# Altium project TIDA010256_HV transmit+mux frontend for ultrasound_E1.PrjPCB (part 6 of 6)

## Sheet 25_RX_Connector.SchDoc
size 431 x 279 mm; Date: Not shown in title block; ApprovedBy: Not shown in title block; CheckedBy: Not shown in title block; Author: Not shown in title block; CompanyName: Not shown in title block; Engineer: Not shown in title block; Organization: Not shown in title block; Address1: Not shown in title block; Address2: Not shown in title block; Address3: Not shown in title block; Address4: Not shown in title block; DocumentNumber: 17; Revision: Use project parameter SCH_Rev; SheetNumber: 17; SheetTotal: 18; PageSetup: Record=PageOptions¦CenterHorizontal=True¦CenterVertical=True¦PrintScale=1.00¦XCorrection=1.00¦YCorrection=1.00¦PrintKind=0¦BorderSize=5000000¦LeftOffset=0¦BottomOffset=0¦Orientation=2¦PaperLength=1000¦PaperWidth=1000¦Scale=100¦PaperSource=15¦PrintQuality=600¦MediaType=1¦DitherType=10¦PaperKind=Letter¦PrintScaleMode=1
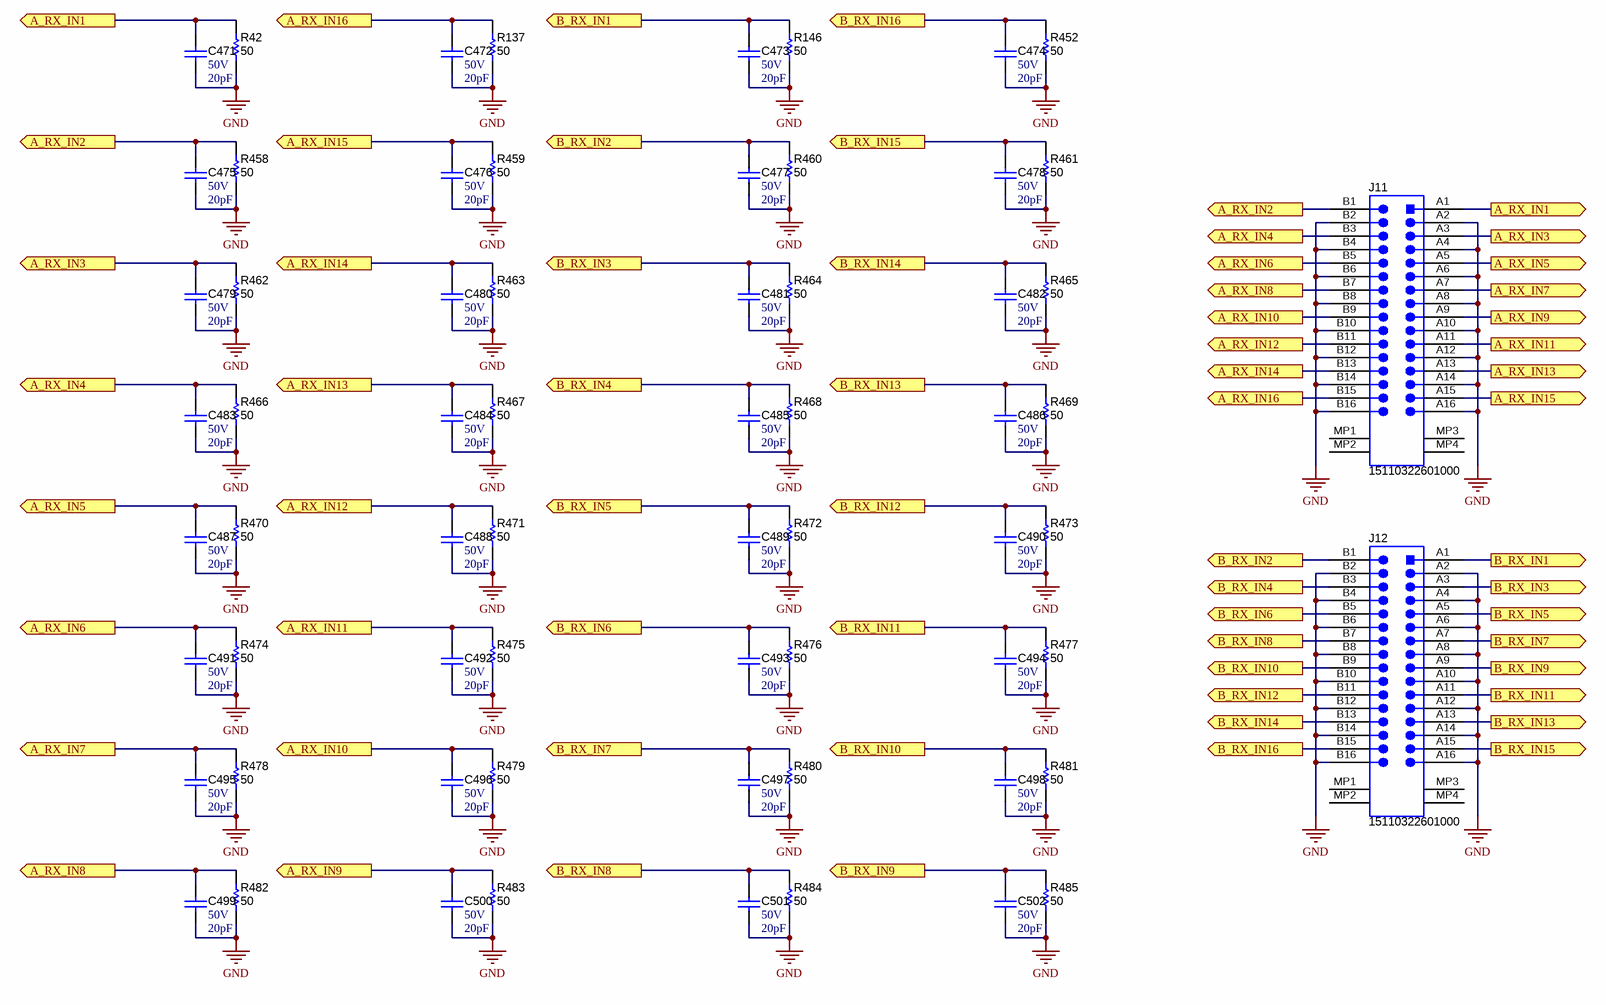
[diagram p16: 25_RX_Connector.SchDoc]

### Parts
C471  VDC_V: 50V  ValueDisplayed: 20pF  [0402]  (hidden comment: C0402C200J5GACTU)
C472  VDC_V: 50V  ValueDisplayed: 20pF  [0402]  (hidden comment: C0402C200J5GACTU)
C473  VDC_V: 50V  ValueDisplayed: 20pF  [0402]  (hidden comment: C0402C200J5GACTU)
C474  VDC_V: 50V  ValueDisplayed: 20pF  [0402]  (hidden comment: C0402C200J5GACTU)
C475  VDC_V: 50V  ValueDisplayed: 20pF  [0402]  (hidden comment: C0402C200J5GACTU)
C476  VDC_V: 50V  ValueDisplayed: 20pF  [0402]  (hidden comment: C0402C200J5GACTU)
C477  VDC_V: 50V  ValueDisplayed: 20pF  [0402]  (hidden comment: C0402C200J5GACTU)
C478  VDC_V: 50V  ValueDisplayed: 20pF  [0402]  (hidden comment: C0402C200J5GACTU)
C479  VDC_V: 50V  ValueDisplayed: 20pF  [0402]  (hidden comment: C0402C200J5GACTU)
C480  VDC_V: 50V  ValueDisplayed: 20pF  [0402]  (hidden comment: C0402C200J5GACTU)
C481  VDC_V: 50V  ValueDisplayed: 20pF  [0402]  (hidden comment: C0402C200J5GACTU)
C482  VDC_V: 50V  ValueDisplayed: 20pF  [0402]  (hidden comment: C0402C200J5GACTU)
C483  VDC_V: 50V  ValueDisplayed: 20pF  [0402]  (hidden comment: C0402C200J5GACTU)
C484  VDC_V: 50V  ValueDisplayed: 20pF  [0402]  (hidden comment: C0402C200J5GACTU)
C485  VDC_V: 50V  ValueDisplayed: 20pF  [0402]  (hidden comment: C0402C200J5GACTU)
C486  VDC_V: 50V  ValueDisplayed: 20pF  [0402]  (hidden comment: C0402C200J5GACTU)
C487  VDC_V: 50V  ValueDisplayed: 20pF  [0402]  (hidden comment: C0402C200J5GACTU)
C488  VDC_V: 50V  ValueDisplayed: 20pF  [0402]  (hidden comment: C0402C200J5GACTU)
C489  VDC_V: 50V  ValueDisplayed: 20pF  [0402]  (hidden comment: C0402C200J5GACTU)
C490  VDC_V: 50V  ValueDisplayed: 20pF  [0402]  (hidden comment: C0402C200J5GACTU)
C491  VDC_V: 50V  ValueDisplayed: 20pF  [0402]  (hidden comment: C0402C200J5GACTU)
C492  VDC_V: 50V  ValueDisplayed: 20pF  [0402]  (hidden comment: C0402C200J5GACTU)
C493  VDC_V: 50V  ValueDisplayed: 20pF  [0402]  (hidden comment: C0402C200J5GACTU)
C494  VDC_V: 50V  ValueDisplayed: 20pF  [0402]  (hidden comment: C0402C200J5GACTU)
C495  VDC_V: 50V  ValueDisplayed: 20pF  [0402]  (hidden comment: C0402C200J5GACTU)
C496  VDC_V: 50V  ValueDisplayed: 20pF  [0402]  (hidden comment: C0402C200J5GACTU)
C497  VDC_V: 50V  ValueDisplayed: 20pF  [0402]  (hidden comment: C0402C200J5GACTU)
C498  VDC_V: 50V  ValueDisplayed: 20pF  [0402]  (hidden comment: C0402C200J5GACTU)
C499  VDC_V: 50V  ValueDisplayed: 20pF  [0402]  (hidden comment: C0402C200J5GACTU)
C500  VDC_V: 50V  ValueDisplayed: 20pF  [0402]  (hidden comment: C0402C200J5GACTU)
C501  VDC_V: 50V  ValueDisplayed: 20pF  [0402]  (hidden comment: C0402C200J5GACTU)
C502  VDC_V: 50V  ValueDisplayed: 20pF  [0402]  (hidden comment: C0402C200J5GACTU)
J11  15110322601000  [Harting_15110322601000]
J12  15110322601000  [Harting_15110322601000]
R42  ValueDisplayed: 50  [0402]  (hidden comment: FC0402E50R0BST1)
R137  ValueDisplayed: 50  [0402]  (hidden comment: FC0402E50R0BST1)
R146  ValueDisplayed: 50  [0402]  (hidden comment: FC0402E50R0BST1)
R452  ValueDisplayed: 50  [0402]  (hidden comment: FC0402E50R0BST1)
R458  ValueDisplayed: 50  [0402]  (hidden comment: FC0402E50R0BST1)
R459  ValueDisplayed: 50  [0402]  (hidden comment: FC0402E50R0BST1)
R460  ValueDisplayed: 50  [0402]  (hidden comment: FC0402E50R0BST1)
R461  ValueDisplayed: 50  [0402]  (hidden comment: FC0402E50R0BST1)
R462  ValueDisplayed: 50  [0402]  (hidden comment: FC0402E50R0BST1)
R463  ValueDisplayed: 50  [0402]  (hidden comment: FC0402E50R0BST1)
R464  ValueDisplayed: 50  [0402]  (hidden comment: FC0402E50R0BST1)
R465  ValueDisplayed: 50  [0402]  (hidden comment: FC0402E50R0BST1)
R466  ValueDisplayed: 50  [0402]  (hidden comment: FC0402E50R0BST1)
R467  ValueDisplayed: 50  [0402]  (hidden comment: FC0402E50R0BST1)
R468  ValueDisplayed: 50  [0402]  (hidden comment: FC0402E50R0BST1)
R469  ValueDisplayed: 50  [0402]  (hidden comment: FC0402E50R0BST1)
R470  ValueDisplayed: 50  [0402]  (hidden comment: FC0402E50R0BST1)
R471  ValueDisplayed: 50  [0402]  (hidden comment: FC0402E50R0BST1)
R472  ValueDisplayed: 50  [0402]  (hidden comment: FC0402E50R0BST1)
R473  ValueDisplayed: 50  [0402]  (hidden comment: FC0402E50R0BST1)
R474  ValueDisplayed: 50  [0402]  (hidden comment: FC0402E50R0BST1)
R475  ValueDisplayed: 50  [0402]  (hidden comment: FC0402E50R0BST1)
R476  ValueDisplayed: 50  [0402]  (hidden comment: FC0402E50R0BST1)
R477  ValueDisplayed: 50  [0402]  (hidden comment: FC0402E50R0BST1)
R478  ValueDisplayed: 50  [0402]  (hidden comment: FC0402E50R0BST1)
R479  ValueDisplayed: 50  [0402]  (hidden comment: FC0402E50R0BST1)
R480  ValueDisplayed: 50  [0402]  (hidden comment: FC0402E50R0BST1)
R481  ValueDisplayed: 50  [0402]  (hidden comment: FC0402E50R0BST1)
R482  ValueDisplayed: 50  [0402]  (hidden comment: FC0402E50R0BST1)
R483  ValueDisplayed: 50  [0402]  (hidden comment: FC0402E50R0BST1)
R484  ValueDisplayed: 50  [0402]  (hidden comment: FC0402E50R0BST1)
R485  ValueDisplayed: 50  [0402]  (hidden comment: FC0402E50R0BST1)

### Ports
A_RX_IN1 (out), A_RX_IN2 (out), A_RX_IN3 (out), A_RX_IN4 (out), A_RX_IN5 (out), A_RX_IN6 (out), A_RX_IN7 (out), A_RX_IN8 (out), A_RX_IN9 (out), A_RX_IN10 (out), A_RX_IN11 (out), A_RX_IN12 (out), A_RX_IN13 (out), A_RX_IN14 (out), A_RX_IN15 (out), A_RX_IN16 (out), B_RX_IN1 (out), B_RX_IN2 (out), B_RX_IN3 (out), B_RX_IN4 (out), B_RX_IN5 (out), B_RX_IN6 (out), B_RX_IN7 (out), B_RX_IN8 (out), B_RX_IN9 (out), B_RX_IN10 (out), B_RX_IN11 (out), B_RX_IN12 (out), B_RX_IN13 (out), B_RX_IN14 (out), B_RX_IN15 (out), B_RX_IN16 (out)

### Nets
GND: C471.2 C472.2 C473.2 C474.2 C475.2 C476.2 C477.2 C478.2 C479.2 C480.2 C481.2 C482.2 C483.2 C484.2 C485.2 C486.2 C487.2 C488.2 C489.2 C490.2 C491.2 C492.2 C493.2 C494.2 C495.2 C496.2 C497.2 C498.2 C499.2 C500.2 C501.2 C502.2 J11.A2 J11.A4 J11.A6 J11.A8 J11.A10 J11.A12 J11.A14 J11.A16 J11.B2 J11.B4 J11.B6 J11.B8 J11.B10 J11.B12 J11.B14 J11.B16 J12.A2 J12.A4 J12.A6 J12.A8 J12.A10 J12.A12 J12.A14 J12.A16 J12.B2 J12.B4 J12.B6 J12.B8 J12.B10 J12.B12 J12.B14 J12.B16 R42.1 R137.1 R146.1 R452.1 R458.1 R459.1 R460.1 R461.1 R462.1 R463.1 R464.1 R465.1 R466.1 R467.1 R468.1 R469.1 R470.1 R471.1 R472.1 R473.1 R474.1 R475.1 R476.1 R477.1 R478.1 R479.1 R480.1 R481.1 R482.1 R483.1 R484.1 R485.1
A_RX_IN1: C471.1 J11.A1 R42.2 ; port A_RX_IN1
A_RX_IN2: C475.1 J11.B1 R458.2 ; port A_RX_IN2
A_RX_IN3: C479.1 J11.A3 R462.2 ; port A_RX_IN3
A_RX_IN4: C483.1 J11.B3 R466.2 ; port A_RX_IN4
A_RX_IN5: C487.1 J11.A5 R470.2 ; port A_RX_IN5
A_RX_IN6: C491.1 J11.B5 R474.2 ; port A_RX_IN6
A_RX_IN7: C495.1 J11.A7 R478.2 ; port A_RX_IN7
A_RX_IN8: C499.1 J11.B7 R482.2 ; port A_RX_IN8
A_RX_IN9: C500.1 J11.A9 R483.2 ; port A_RX_IN9
A_RX_IN10: C496.1 J11.B9 R479.2 ; port A_RX_IN10
A_RX_IN11: C492.1 J11.A11 R475.2 ; port A_RX_IN11
A_RX_IN12: C488.1 J11.B11 R471.2 ; port A_RX_IN12
A_RX_IN13: C484.1 J11.A13 R467.2 ; port A_RX_IN13
A_RX_IN14: C480.1 J11.B13 R463.2 ; port A_RX_IN14
A_RX_IN15: C476.1 J11.A15 R459.2 ; port A_RX_IN15
A_RX_IN16: C472.1 J11.B15 R137.2 ; port A_RX_IN16
B_RX_IN1: C473.1 J12.A1 R146.2 ; port B_RX_IN1
B_RX_IN2: C477.1 J12.B1 R460.2 ; port B_RX_IN2
B_RX_IN3: C481.1 J12.A3 R464.2 ; port B_RX_IN3
B_RX_IN4: C485.1 J12.B3 R468.2 ; port B_RX_IN4
B_RX_IN5: C489.1 J12.A5 R472.2 ; port B_RX_IN5
B_RX_IN6: C493.1 J12.B5 R476.2 ; port B_RX_IN6
B_RX_IN7: C497.1 J12.A7 R480.2 ; port B_RX_IN7
B_RX_IN8: C501.1 J12.B7 R484.2 ; port B_RX_IN8
B_RX_IN9: C502.1 J12.A9 R485.2 ; port B_RX_IN9
B_RX_IN10: C498.1 J12.B9 R481.2 ; port B_RX_IN10
B_RX_IN11: C494.1 J12.A11 R477.2 ; port B_RX_IN11
B_RX_IN12: C490.1 J12.B11 R473.2 ; port B_RX_IN12
B_RX_IN13: C486.1 J12.A13 R469.2 ; port B_RX_IN13
B_RX_IN14: C482.1 J12.B13 R465.2 ; port B_RX_IN14
B_RX_IN15: C478.1 J12.A15 R461.2 ; port B_RX_IN15
B_RX_IN16: C474.1 J12.B15 R452.2 ; port B_RX_IN16

Not connected (* = marked no-connect by the designer): J11 MP1 MP2 MP3 MP4; J12 MP1 MP2 MP3 MP4

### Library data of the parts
C471-C502 = CMP-0006241-2: CAP, CERM, 20 pF, 50 V, +/- 5%, C0G/NP0, 0402; Manufacturer: Kemet; TaMin_C: -55°C; Polarized: N; SizeAreaWB_mm2: 3; Value1: Unknown; U/M: EA; Value: 20pF; TaMax_C: 125°C; SizeZ_mm: 0.6; SizeX_mm: 1; SizeY_mm: 0.5; AEC Category: Q200
J11 J12 = CMP-0084279-1: Header (Shrouded), 1.27mm, 16x2, Gold, SMT; Manufacturer: Harting; Shrouded: Y; Pitch_mm: 1.27; Row_Count: 2; Voltage_V: 500V; Gender: Male
R42 R137 R146 R452 R458-R485 = CMP-0026791-1: RES, 50, 0.1%, 0.05 W, 0402; Manufacturer: Vishay-Dale; Power_W: 50mW; TempCo: 25 ppm/C; Value_Code: 50R0; U/M: EA; Value: 50; SizeX_mm: 1; SizeY_mm: 0.5; SizeZ_mm: 0.6; Value2: 0.05W; CompType: Resistor; AEC Qualified: N; AEC Category: Q200

## Sheet Hardware.SchDoc
size 431 x 279 mm; Date: Not shown in title block; ApprovedBy: Not shown in title block; CheckedBy: Not shown in title block; Author: Not shown in title block; CompanyName: Not shown in title block; DrawnBy: Jason Ding; Engineer: Not shown in title block; Organization: Not shown in title block; Address1: Not shown in title block; Address2: Not shown in title block; Address3: Not shown in title block; Address4: Not shown in title block; DocumentNumber: 18; Revision: Use project parameter SCH_Rev; SheetNumber: 18; SheetTotal: 18; PageSetup: Record=PageOptions¦CenterHorizontal=True¦CenterVertical=True¦PrintScale=1.00¦XCorrection=1.00¦YCorrection=1.00¦PrintKind=0¦BorderSize=5000000¦LeftOffset=0¦BottomOffset=0¦Orientation=2¦PaperLength=1000¦PaperWidth=1000¦Scale=100¦PaperSource=15¦PrintQuality=600¦MediaType=1¦DitherType=10¦PaperKind=Letter¦PrintScaleMode=1
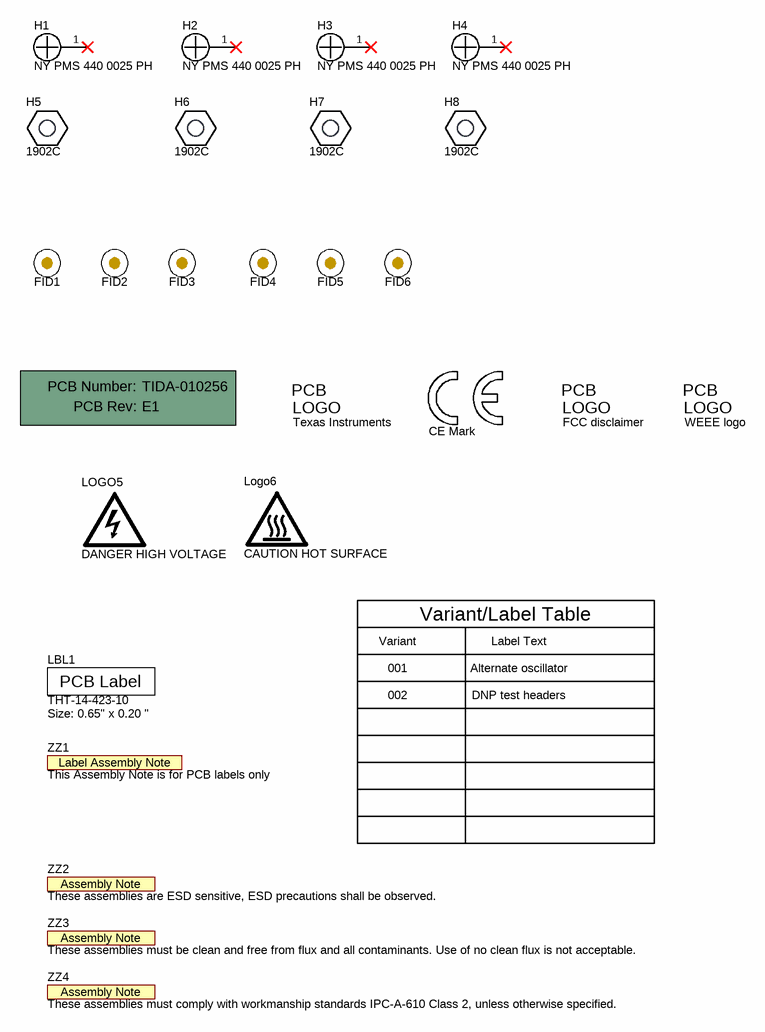
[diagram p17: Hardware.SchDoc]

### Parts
!PCB  Printed Circuit Board  (value not drawn)  (mechanical)
FID1  Fiducial  [Fiducial10-20]  (value not drawn)
FID2  Fiducial  [Fiducial10-20]  (value not drawn)
FID3  Fiducial  [Fiducial10-20]  (value not drawn)
FID4  Fiducial  [Fiducial10-20]  (value not drawn)
FID5  Fiducial  [Fiducial10-20]  (value not drawn)
FID6  Fiducial  [Fiducial10-20]  (value not drawn)
H1  NY PMS 440 0025 PH  [NY PMS 440 0025 PH]
H2  NY PMS 440 0025 PH  [NY PMS 440 0025 PH]
H3  NY PMS 440 0025 PH  [NY PMS 440 0025 PH]
H4  NY PMS 440 0025 PH  [NY PMS 440 0025 PH]
H5  1902C  [Keystone_1902C]
H6  1902C  [Keystone_1902C]
H7  1902C  [Keystone_1902C]
H8  1902C  [Keystone_1902C]
LBL1  THT-14-423-10  Note: Size: 0.65" x 0.20 "  [Label_650x200]
Logo1  Texas Instruments  [TI_Stacked_Overlay_Small]  (no BOM)
Logo2  CE Mark  [CE_Mark_5mm]  (no BOM)
Logo3  FCC disclaimer  [FCC_disclaimer]  (no BOM)
Logo4  WEEE logo  [WEEE_Minimum]  (no BOM)
LOGO5  DANGER HIGH VOLTAGE  [IEC_HighVoltage_Large]  (no BOM)
Logo6  CAUTION HOT SURFACE  [IEC_HotSurface_Large]  (no BOM)
ZZ1  This Assembly Note is for PCB labels only  [AssemblyNoteLabel]  (no BOM)
ZZ2  These assemblies are ESD sensitive, ESD precautions shall be observed.  [AssemblyNote]  (no BOM)
ZZ3  These assemblies must be clean and free from flux and all contaminants. Use of no clean flux is not acceptable.  [AssemblyNote]  (no BOM)
ZZ4  These assemblies must comply with workmanship standards IPC-A-610 Class 2, unless otherwise specified.  [AssemblyNote]  (no BOM)

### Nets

Not connected (* = marked no-connect by the designer): H1 1*; H2 1*; H3 1*; H4 1*

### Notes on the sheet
- Variant
- Variant/Label Table
- Label Text
- 001
- 002
- Alternate oscillator
- DNP test headers

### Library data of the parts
!PCB = CMP-0003618-2: Manufacturer: Any; PartNumber: TIDA-010256
FID1-FID6 = CMP-0077181-1: Fiducial mark.  There is nothing to buy or mount.
H1-H4 = CMP-0003617-1: Machine Screw, Round, #4-40 x 1/4, Nylon, Philips panhead; Manufacturer: B&F Fastener Supply; CompType: Hardware
H5-H8 = CMP-0003610-1: Standoff, Hex, 0.5"L #4-40 Nylon; Manufacturer: Keystone; CompType: Hardware
LBL1 = CMP-0003625-1: Thermal Transfer Printable Labels, 0.650" W x 0.200" H - 10,000 per roll; Manufacturer: Brady; CompType: Label
Logo1 = CMP-0074838-1: Texas Instrument Corporate Signature; SymbolCreator: a0412235; Lib Reference: TI_Logo; Library Reference: Logo
Logo2 = CMP-0074844-1: SymbolCreator: a0412235
Logo3 = CMP-0074847-1: FCC_disclaimer; Library Reference: Logo
Logo4 = CMP-0074769-3: Manufacturer: Texas Instruments; CompType: IC; AEC Category: Q200
LOGO5 = CMP-0074835-1: IEC 61010-1 High Voltage Warning; SymbolCreator: a0412235
Logo6 = CMP-0074837-2: IEC 61010-1 Hot Surface Warning; Manufacturer: Texas Instruments; CompType: IC; AEC Category: Q200; SymbolCreator: a0412235
ZZ1 = CMP-0003616-3
ZZ2 = CMP-0077236-1
ZZ3 = CMP-0077237-1
ZZ4 = CMP-0077238-1

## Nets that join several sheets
GND: 11_HighVoltage_PowerSupply (15 pins), 12_LowVoltage_PowerSupplies01 (82 pins), 13_LowVoltage_PowerSupplies02 (35 pins), 14_XDS110_Debugger (59 pins), 15_AM243x_BootMode (28 pins), 16_AM243x_Reset (28 pins), 17_AM243x_SocPower (137 pins), 18_AM243x_Pinout (37 pins), 19_Clock_Gen (24 pins), 20_TX7516_PartAPinout (82 pins), 21_TX7516_PartBPinout (78 pins), 22_TMUX9832(0-64)_Pinout (38 pins), 23_TMUX9832(65-128)_Pinout (40 pins), 24_TX_Connector(no load resitor) (112 pins), 25_RX_Connector (96 pins)
MHV_A: 11_HighVoltage_PowerSupply (D18.2 D19.2), 20_TX7516_PartAPinout (12 pins), 21_TX7516_PartBPinout (12 pins)
MHV_B: 11_HighVoltage_PowerSupply (D23.2 D24.2), 20_TX7516_PartAPinout (12 pins), 21_TX7516_PartBPinout (12 pins)
PHV_A: 11_HighVoltage_PowerSupply (D15.1 D17.1), 20_TX7516_PartAPinout (12 pins), 21_TX7516_PartBPinout (12 pins)
PHV_B: 11_HighVoltage_PowerSupply (D20.1 D22.1), 20_TX7516_PartAPinout (12 pins), 21_TX7516_PartBPinout (12 pins)
V_+12V: 11_HighVoltage_PowerSupply (12 pins), 12_LowVoltage_PowerSupplies01 (21 pins), 13_LowVoltage_PowerSupplies02 (7 pins)
A_RX_IN1: 20_TX7516_PartAPinout (U25.L12), 25_RX_Connector (C471.1 J11.A1 R42.2)
A_RX_IN2: 20_TX7516_PartAPinout (U25.M12), 25_RX_Connector (C475.1 J11.B1 R458.2)
A_RX_IN3: 20_TX7516_PartAPinout (U25.L11), 25_RX_Connector (C479.1 J11.A3 R462.2)
A_RX_IN4: 20_TX7516_PartAPinout (U25.M11), 25_RX_Connector (C483.1 J11.B3 R466.2)
A_RX_IN5: 20_TX7516_PartAPinout (U25.L10), 25_RX_Connector (C487.1 J11.A5 R470.2)
A_RX_IN6: 20_TX7516_PartAPinout (U25.M10), 25_RX_Connector (C491.1 J11.B5 R474.2)
A_RX_IN7: 20_TX7516_PartAPinout (U25.L9), 25_RX_Connector (C495.1 J11.A7 R478.2)
A_RX_IN8: 20_TX7516_PartAPinout (U25.M9), 25_RX_Connector (C499.1 J11.B7 R482.2)
A_RX_IN9: 20_TX7516_PartAPinout (U25.L4), 25_RX_Connector (C500.1 J11.A9 R483.2)
A_RX_IN10: 20_TX7516_PartAPinout (U25.M4), 25_RX_Connector (C496.1 J11.B9 R479.2)
A_RX_IN11: 20_TX7516_PartAPinout (U25.L3), 25_RX_Connector (C492.1 J11.A11 R475.2)
A_RX_IN12: 20_TX7516_PartAPinout (U25.M3), 25_RX_Connector (C488.1 J11.B11 R471.2)
A_RX_IN13: 20_TX7516_PartAPinout (U25.L2), 25_RX_Connector (C484.1 J11.A13 R467.2)
A_RX_IN14: 20_TX7516_PartAPinout (U25.M2), 25_RX_Connector (C480.1 J11.B13 R463.2)
A_RX_IN15: 20_TX7516_PartAPinout (U25.L1), 25_RX_Connector (C476.1 J11.A15 R459.2)
A_RX_IN16: 20_TX7516_PartAPinout (U25.M1), 25_RX_Connector (C472.1 J11.B15 R137.2)
A_TX_OUT1: 20_TX7516_PartAPinout (U25.A12), 22_TMUX9832(0-64)_Pinout (J14.1 U28.K2 U29.K2), 23_TMUX9832(65-128)_Pinout (J16.1 U27.K2 U30.K2)
A_TX_OUT2: 20_TX7516_PartAPinout (U25.B12), 22_TMUX9832(0-64)_Pinout (U28.L3 U29.L3), 23_TMUX9832(65-128)_Pinout (U27.L3 U30.L3)
A_TX_OUT3: 20_TX7516_PartAPinout (U25.C12), 22_TMUX9832(0-64)_Pinout (J13.1 U28.K3 U29.K3), 23_TMUX9832(65-128)_Pinout (U27.K3 U30.K3)
A_TX_OUT4: 20_TX7516_PartAPinout (U25.A11), 22_TMUX9832(0-64)_Pinout (U28.L4 U29.L4), 23_TMUX9832(65-128)_Pinout (U27.L4 U30.L4)
A_TX_OUT5: 20_TX7516_PartAPinout (U25.B11), 22_TMUX9832(0-64)_Pinout (U28.K4 U29.K4), 23_TMUX9832(65-128)_Pinout (U27.K4 U30.K4)
A_TX_OUT6: 20_TX7516_PartAPinout (U25.C11), 22_TMUX9832(0-64)_Pinout (U28.L5 U29.L5), 23_TMUX9832(65-128)_Pinout (U27.L5 U30.L5)
A_TX_OUT7: 20_TX7516_PartAPinout (U25.A10), 22_TMUX9832(0-64)_Pinout (U28.K5 U29.K5), 23_TMUX9832(65-128)_Pinout (U27.K5 U30.K5)
A_TX_OUT8: 20_TX7516_PartAPinout (U25.B10), 22_TMUX9832(0-64)_Pinout (U28.L6 U29.L6), 23_TMUX9832(65-128)_Pinout (U27.L6 U30.L6)
A_TX_OUT9: 20_TX7516_PartAPinout (U25.A1), 22_TMUX9832(0-64)_Pinout (U28.B5 U29.B5), 23_TMUX9832(65-128)_Pinout (U27.B5 U30.B5)
A_TX_OUT10: 20_TX7516_PartAPinout (U25.B1), 22_TMUX9832(0-64)_Pinout (U28.A5 U29.A5), 23_TMUX9832(65-128)_Pinout (U27.A5 U30.A5)
A_TX_OUT11: 20_TX7516_PartAPinout (U25.C1), 22_TMUX9832(0-64)_Pinout (U28.B4 U29.B4), 23_TMUX9832(65-128)_Pinout (U27.B4 U30.B4)
A_TX_OUT12: 20_TX7516_PartAPinout (U25.A2), 22_TMUX9832(0-64)_Pinout (U28.A4 U29.A4), 23_TMUX9832(65-128)_Pinout (U27.A4 U30.A4)
A_TX_OUT13: 20_TX7516_PartAPinout (U25.B2), 22_TMUX9832(0-64)_Pinout (U28.B3 U29.B3), 23_TMUX9832(65-128)_Pinout (U27.B3 U30.B3)
A_TX_OUT14: 20_TX7516_PartAPinout (U25.C2), 22_TMUX9832(0-64)_Pinout (U28.A3 U29.A3), 23_TMUX9832(65-128)_Pinout (U27.A3 U30.A3)
A_TX_OUT15: 20_TX7516_PartAPinout (U25.A3), 22_TMUX9832(0-64)_Pinout (U28.A1 U29.A1), 23_TMUX9832(65-128)_Pinout (U27.A1 U30.A1)
A_TX_OUT16: 20_TX7516_PartAPinout (U25.B3), 22_TMUX9832(0-64)_Pinout (U28.B1 U29.B1), 23_TMUX9832(65-128)_Pinout (U27.B1 U30.B1)
B_RX_IN1: 21_TX7516_PartBPinout (U26.L12), 25_RX_Connector (C473.1 J12.A1 R146.2)
B_RX_IN2: 21_TX7516_PartBPinout (U26.M12), 25_RX_Connector (C477.1 J12.B1 R460.2)
B_RX_IN3: 21_TX7516_PartBPinout (U26.L11), 25_RX_Connector (C481.1 J12.A3 R464.2)
B_RX_IN4: 21_TX7516_PartBPinout (U26.M11), 25_RX_Connector (C485.1 J12.B3 R468.2)
B_RX_IN5: 21_TX7516_PartBPinout (U26.L10), 25_RX_Connector (C489.1 J12.A5 R472.2)
B_RX_IN6: 21_TX7516_PartBPinout (U26.M10), 25_RX_Connector (C493.1 J12.B5 R476.2)
B_RX_IN7: 21_TX7516_PartBPinout (U26.L9), 25_RX_Connector (C497.1 J12.A7 R480.2)
B_RX_IN8: 21_TX7516_PartBPinout (U26.M9), 25_RX_Connector (C501.1 J12.B7 R484.2)
B_RX_IN9: 21_TX7516_PartBPinout (U26.L4), 25_RX_Connector (C502.1 J12.A9 R485.2)
B_RX_IN10: 21_TX7516_PartBPinout (U26.M4), 25_RX_Connector (C498.1 J12.B9 R481.2)
B_RX_IN11: 21_TX7516_PartBPinout (U26.L3), 25_RX_Connector (C494.1 J12.A11 R477.2)
B_RX_IN12: 21_TX7516_PartBPinout (U26.M3), 25_RX_Connector (C490.1 J12.B11 R473.2)
B_RX_IN13: 21_TX7516_PartBPinout (U26.L2), 25_RX_Connector (C486.1 J12.A13 R469.2)
B_RX_IN14: 21_TX7516_PartBPinout (U26.M2), 25_RX_Connector (C482.1 J12.B13 R465.2)
B_RX_IN15: 21_TX7516_PartBPinout (U26.L1), 25_RX_Connector (C478.1 J12.A15 R461.2)
B_RX_IN16: 21_TX7516_PartBPinout (U26.M1), 25_RX_Connector (C474.1 J12.B15 R452.2)
B_SYNC_N: 20_TX7516_PartAPinout (R431.1 R432.1 R433.2), 21_TX7516_PartBPinout (U26.L6)
B_SYNC_P: 20_TX7516_PartAPinout (R430.2 R431.2 R432.2), 21_TX7516_PartBPinout (U26.L7)
B_TX_OUT1: 21_TX7516_PartBPinout (U26.A12), 22_TMUX9832(0-64)_Pinout (U28.B11 U29.B11), 23_TMUX9832(65-128)_Pinout (U27.B11 U30.B11)
B_TX_OUT2: 21_TX7516_PartBPinout (U26.B12), 22_TMUX9832(0-64)_Pinout (U28.A11 U29.A11), 23_TMUX9832(65-128)_Pinout (U27.A11 U30.A11)
B_TX_OUT3: 21_TX7516_PartBPinout (U26.C12), 22_TMUX9832(0-64)_Pinout (U28.A9 U29.A9), 23_TMUX9832(65-128)_Pinout (U27.A9 U30.A9)
B_TX_OUT4: 21_TX7516_PartBPinout (U26.A11), 22_TMUX9832(0-64)_Pinout (U28.B9 U29.B9), 23_TMUX9832(65-128)_Pinout (U27.B9 U30.B9)
B_TX_OUT5: 21_TX7516_PartBPinout (U26.B11), 22_TMUX9832(0-64)_Pinout (U28.A8 U29.A8), 23_TMUX9832(65-128)_Pinout (U27.A8 U30.A8)
B_TX_OUT6: 21_TX7516_PartBPinout (U26.C11), 22_TMUX9832(0-64)_Pinout (U28.B8 U29.B8), 23_TMUX9832(65-128)_Pinout (U27.B8 U30.B8)
B_TX_OUT7: 21_TX7516_PartBPinout (U26.A10), 22_TMUX9832(0-64)_Pinout (U28.A7 U29.A7), 23_TMUX9832(65-128)_Pinout (U27.A7 U30.A7)
B_TX_OUT8: 21_TX7516_PartBPinout (U26.B10), 22_TMUX9832(0-64)_Pinout (U28.B7 U29.B7), 23_TMUX9832(65-128)_Pinout (U27.B7 U30.B7)
B_TX_OUT9: 21_TX7516_PartBPinout (U26.A1), 22_TMUX9832(0-64)_Pinout (U28.K6 U29.K6), 23_TMUX9832(65-128)_Pinout (U27.K6 U30.K6)
B_TX_OUT10: 21_TX7516_PartBPinout (U26.B1), 22_TMUX9832(0-64)_Pinout (U28.K7 U29.K7), 23_TMUX9832(65-128)_Pinout (U27.K7 U30.K7)
B_TX_OUT11: 21_TX7516_PartBPinout (U26.C1), 22_TMUX9832(0-64)_Pinout (U28.L7 U29.L7), 23_TMUX9832(65-128)_Pinout (U27.L7 U30.L7)
B_TX_OUT12: 21_TX7516_PartBPinout (U26.A2), 22_TMUX9832(0-64)_Pinout (U28.K8 U29.K8), 23_TMUX9832(65-128)_Pinout (U27.K8 U30.K8)
B_TX_OUT13: 21_TX7516_PartBPinout (U26.B2), 22_TMUX9832(0-64)_Pinout (U28.L8 U29.L8), 23_TMUX9832(65-128)_Pinout (U27.L8 U30.L8)
B_TX_OUT14: 21_TX7516_PartBPinout (U26.C2), 22_TMUX9832(0-64)_Pinout (U28.K9 U29.K9), 23_TMUX9832(65-128)_Pinout (U27.K9 U30.K9)
B_TX_OUT15: 21_TX7516_PartBPinout (U26.A3), 22_TMUX9832(0-64)_Pinout (U28.L9 U29.L9), 23_TMUX9832(65-128)_Pinout (U27.L9 U30.L9)
B_TX_OUT16: 21_TX7516_PartBPinout (U26.B3), 22_TMUX9832(0-64)_Pinout (U28.K10 U29.K10), 23_TMUX9832(65-128)_Pinout (J18.1 U27.K10 U30.K10)
LP_3: 22_TMUX9832(0-64)_Pinout (R509.2 U28.G6), 23_TMUX9832(65-128)_Pinout (R502.1)
NetC96_1: 13_LowVoltage_PowerSupplies02 (C96.1 U11.5), 17_AM243x_SocPower (U17.E16)
NetQ2_1: 11_HighVoltage_PowerSupply (Q2.1 Q4.1 R20.2 R32.2), 18_AM243x_Pinout (U17.Y15)
NetQ5_3: 15_AM243x_BootMode (Q5.3 R123.2), 18_AM243x_Pinout (U17.AA14)
NetQ6_3: 15_AM243x_BootMode (Q6.3 R124.2), 18_AM243x_Pinout (U17.AA13)
NetR1_1: 11_HighVoltage_PowerSupply (R1.1 R6.1 U1.2 U2.2), 18_AM243x_Pinout (U35.8)
NetR2_1: 11_HighVoltage_PowerSupply (R2.1 R7.1 U1.3 U2.3), 18_AM243x_Pinout (U35.1)
NetR54_1: 12_LowVoltage_PowerSupplies01 (R54.1 U32.4), 13_LowVoltage_PowerSupplies02 (R67.2)
NetR58_2: 12_LowVoltage_PowerSupplies01 (R58.2), 13_LowVoltage_PowerSupplies02 (R63.1 U9.4)
NetR81_1: 14_XDS110_Debugger (R81.1 U15.6), 18_AM243x_Pinout (U17.B11)
NetR428_2: 18_AM243x_Pinout (R428.2 U17.E2), 20_TX7516_PartAPinout (R515.1 U31.7)
NetR429_2: 18_AM243x_Pinout (R429.2 U17.D1), 20_TX7516_PartAPinout (R516.1 U31.15)
NetR438_2: 18_AM243x_Pinout (U17.F2), 20_TX7516_PartAPinout (R438.2 U31.4)
NetR439_2: 18_AM243x_Pinout (U17.E1), 20_TX7516_PartAPinout (R439.2 U31.12)
NetR443_1: 15_AM243x_BootMode (R443.1), 18_AM243x_Pinout (U17.P20)
NetR445_1: 15_AM243x_BootMode (R445.1 U33.7), 18_AM243x_Pinout (U17.L20)
NetR446_1: 15_AM243x_BootMode (R446.1 U34.1), 18_AM243x_Pinout (U17.M20)
NetR447_1: 15_AM243x_BootMode (R447.1), 16_AM243x_Reset (R448.2 U17.A6)
NetR488_1: 18_AM243x_Pinout (U17.G2), 22_TMUX9832(0-64)_Pinout (R488.1)
NetR492_2: 22_TMUX9832(0-64)_Pinout (R492.2), 23_TMUX9832(65-128)_Pinout (U27.H4)
NetR504_1: 22_TMUX9832(0-64)_Pinout (U28.F7), 23_TMUX9832(65-128)_Pinout (R504.1)
NetR513_2: 18_AM243x_Pinout (R513.2 U17.B7), 20_TX7516_PartAPinout (U25.H4)
NetR514_2: 18_AM243x_Pinout (R514.2 U17.B9), 21_TX7516_PartBPinout (U26.H4)
NetU12_35: 14_XDS110_Debugger (U12.35), 18_AM243x_Pinout (U20.13)
NetU12_36: 14_XDS110_Debugger (U12.36), 18_AM243x_Pinout (U20.11)
NetU12_37: 14_XDS110_Debugger (U12.37), 18_AM243x_Pinout (U21.7)
NetU12_38: 14_XDS110_Debugger (U12.38), 18_AM243x_Pinout (U20.12)
NetU12_40: 14_XDS110_Debugger (U12.40), 18_AM243x_Pinout (U20.10)
NetU12_42: 14_XDS110_Debugger (U12.42), 18_AM243x_Pinout (U22.8)
NetU12_43: 14_XDS110_Debugger (U12.43), 18_AM243x_Pinout (U22.1)
NetU15_4: 14_XDS110_Debugger (U15.4), 18_AM243x_Pinout (U17.B10)
NetU17_A8: 18_AM243x_Pinout (U17.A8), 20_TX7516_PartAPinout (U25.H9), 21_TX7516_PartBPinout (U26.H9)
NetU17_A17: 18_AM243x_Pinout (U17.A17), 20_TX7516_PartAPinout (U25.J12), 21_TX7516_PartBPinout (U26.J12)
NetU17_B8: 18_AM243x_Pinout (U17.B8), 20_TX7516_PartAPinout (U25.H6), 21_TX7516_PartBPinout (U26.H6)
NetU17_B15: 18_AM243x_Pinout (U17.B15), 20_TX7516_PartAPinout (U25.G4), 21_TX7516_PartBPinout (U26.G4)
NetU17_B16: 18_AM243x_Pinout (U17.B16), 20_TX7516_PartAPinout (U25.J1), 21_TX7516_PartBPinout (U26.J1)
NetU17_C9: 18_AM243x_Pinout (U17.C9), 20_TX7516_PartAPinout (U25.H12), 21_TX7516_PartBPinout (U26.H12)
NetU17_L19: 15_AM243x_BootMode (U33.15), 18_AM243x_Pinout (U17.L19)
NetU17_L21: 15_AM243x_BootMode (U33.9), 18_AM243x_Pinout (U17.L21)
NetU17_N1: 18_AM243x_Pinout (U17.N1), 22_TMUX9832(0-64)_Pinout (U29.H4)
NetU17_N3: 18_AM243x_Pinout (U17.N3), 22_TMUX9832(0-64)_Pinout (U29.F5)
NetU17_N19: 15_AM243x_BootMode (U33.1), 18_AM243x_Pinout (U17.N19)
NetU17_N20: 15_AM243x_BootMode (U33.8), 18_AM243x_Pinout (U17.N20)
TX1_CLK_N: 19_Clock_Gen (U23.7), 20_TX7516_PartAPinout (C238.2)
TX1_CLK_P: 19_Clock_Gen (U23.6), 20_TX7516_PartAPinout (C237.2)
TX2_CLK_N: 19_Clock_Gen (U23.4), 21_TX7516_PartBPinout (C269.2)
TX2_CLK_P: 19_Clock_Gen (U23.3), 21_TX7516_PartBPinout (C268.2)
TX_OUT1: 22_TMUX9832(0-64)_Pinout (J7.1 U29.L1), 24_TX_Connector(no load resitor) (J10.2)
TX_OUT2: 22_TMUX9832(0-64)_Pinout (U29.K1), 24_TX_Connector(no load resitor) (J9.119)
TX_OUT3: 22_TMUX9832(0-64)_Pinout (J8.1 U29.J2), 24_TX_Connector(no load resitor) (J10.4)
TX_OUT4: 22_TMUX9832(0-64)_Pinout (U29.J1), 24_TX_Connector(no load resitor) (J9.117)
TX_OUT5: 22_TMUX9832(0-64)_Pinout (U29.H2), 24_TX_Connector(no load resitor) (J10.8)
TX_OUT6: 22_TMUX9832(0-64)_Pinout (U29.H1), 24_TX_Connector(no load resitor) (J9.113)
TX_OUT7: 22_TMUX9832(0-64)_Pinout (U29.G2), 24_TX_Connector(no load resitor) (J10.12)
TX_OUT8: 22_TMUX9832(0-64)_Pinout (U29.G1), 24_TX_Connector(no load resitor) (J9.109)
TX_OUT9: 22_TMUX9832(0-64)_Pinout (U29.F2), 24_TX_Connector(no load resitor) (J10.16)
TX_OUT10: 22_TMUX9832(0-64)_Pinout (U29.F1), 24_TX_Connector(no load resitor) (J9.105)
TX_OUT11: 22_TMUX9832(0-64)_Pinout (U29.E2), 24_TX_Connector(no load resitor) (J10.20)
TX_OUT12: 22_TMUX9832(0-64)_Pinout (U29.E1), 24_TX_Connector(no load resitor) (J9.101)
TX_OUT13: 22_TMUX9832(0-64)_Pinout (U29.D2), 24_TX_Connector(no load resitor) (J10.24)
TX_OUT14: 22_TMUX9832(0-64)_Pinout (U29.D1), 24_TX_Connector(no load resitor) (J9.97)
TX_OUT15: 22_TMUX9832(0-64)_Pinout (U29.C2), 24_TX_Connector(no load resitor) (J10.28)
TX_OUT16: 22_TMUX9832(0-64)_Pinout (U29.C1), 24_TX_Connector(no load resitor) (J9.93)
TX_OUT17: 22_TMUX9832(0-64)_Pinout (U29.C11), 24_TX_Connector(no load resitor) (J10.32)
TX_OUT18: 22_TMUX9832(0-64)_Pinout (U29.C10), 24_TX_Connector(no load resitor) (J9.89)
TX_OUT19: 22_TMUX9832(0-64)_Pinout (U29.D11), 24_TX_Connector(no load resitor) (J10.36)
TX_OUT20: 22_TMUX9832(0-64)_Pinout (U29.D10), 24_TX_Connector(no load resitor) (J9.85)
TX_OUT21: 22_TMUX9832(0-64)_Pinout (U29.E11), 24_TX_Connector(no load resitor) (J10.40)
TX_OUT22: 22_TMUX9832(0-64)_Pinout (U29.E10), 24_TX_Connector(no load resitor) (J9.81)
TX_OUT23: 22_TMUX9832(0-64)_Pinout (U29.F11), 24_TX_Connector(no load resitor) (J10.44)
TX_OUT24: 22_TMUX9832(0-64)_Pinout (U29.F10), 24_TX_Connector(no load resitor) (J9.77)
TX_OUT25: 22_TMUX9832(0-64)_Pinout (U29.G11), 24_TX_Connector(no load resitor) (J10.48)
TX_OUT26: 22_TMUX9832(0-64)_Pinout (U29.G10), 24_TX_Connector(no load resitor) (J9.73)
TX_OUT27: 22_TMUX9832(0-64)_Pinout (U29.H11), 24_TX_Connector(no load resitor) (J10.52)
TX_OUT28: 22_TMUX9832(0-64)_Pinout (U29.H10), 24_TX_Connector(no load resitor) (J9.69)
TX_OUT29: 22_TMUX9832(0-64)_Pinout (U29.J11), 24_TX_Connector(no load resitor) (J10.56)
TX_OUT30: 22_TMUX9832(0-64)_Pinout (U29.J10), 24_TX_Connector(no load resitor) (J9.65)
TX_OUT31: 22_TMUX9832(0-64)_Pinout (U29.K11), 24_TX_Connector(no load resitor) (J10.60)
TX_OUT32: 22_TMUX9832(0-64)_Pinout (U29.L11), 24_TX_Connector(no load resitor) (J9.61)
TX_OUT33: 22_TMUX9832(0-64)_Pinout (U28.L1), 24_TX_Connector(no load resitor) (J10.1)
TX_OUT34: 22_TMUX9832(0-64)_Pinout (U28.K1), 24_TX_Connector(no load resitor) (J9.120)
TX_OUT35: 22_TMUX9832(0-64)_Pinout (U28.J2), 24_TX_Connector(no load resitor) (J10.3)
TX_OUT36: 22_TMUX9832(0-64)_Pinout (U28.J1), 24_TX_Connector(no load resitor) (J9.118)
TX_OUT37: 22_TMUX9832(0-64)_Pinout (U28.H2), 24_TX_Connector(no load resitor) (J10.7)
TX_OUT38: 22_TMUX9832(0-64)_Pinout (U28.H1), 24_TX_Connector(no load resitor) (J9.114)
TX_OUT39: 22_TMUX9832(0-64)_Pinout (U28.G2), 24_TX_Connector(no load resitor) (J10.11)
TX_OUT40: 22_TMUX9832(0-64)_Pinout (U28.G1), 24_TX_Connector(no load resitor) (J9.110)
TX_OUT41: 22_TMUX9832(0-64)_Pinout (U28.F2), 24_TX_Connector(no load resitor) (J10.15)
TX_OUT42: 22_TMUX9832(0-64)_Pinout (U28.F1), 24_TX_Connector(no load resitor) (J9.106)
TX_OUT43: 22_TMUX9832(0-64)_Pinout (U28.E2), 24_TX_Connector(no load resitor) (J10.19)
TX_OUT44: 22_TMUX9832(0-64)_Pinout (U28.E1), 24_TX_Connector(no load resitor) (J9.102)
TX_OUT45: 22_TMUX9832(0-64)_Pinout (U28.D2), 24_TX_Connector(no load resitor) (J10.23)
TX_OUT46: 22_TMUX9832(0-64)_Pinout (U28.D1), 24_TX_Connector(no load resitor) (J9.98)
TX_OUT47: 22_TMUX9832(0-64)_Pinout (U28.C2), 24_TX_Connector(no load resitor) (J10.27)
TX_OUT48: 22_TMUX9832(0-64)_Pinout (U28.C1), 24_TX_Connector(no load resitor) (J9.94)
TX_OUT49: 22_TMUX9832(0-64)_Pinout (U28.C11), 24_TX_Connector(no load resitor) (J10.31)
TX_OUT50: 22_TMUX9832(0-64)_Pinout (U28.C10), 24_TX_Connector(no load resitor) (J9.90)
TX_OUT51: 22_TMUX9832(0-64)_Pinout (U28.D11), 24_TX_Connector(no load resitor) (J10.35)
TX_OUT52: 22_TMUX9832(0-64)_Pinout (U28.D10), 24_TX_Connector(no load resitor) (J9.86)
TX_OUT53: 22_TMUX9832(0-64)_Pinout (U28.E11), 24_TX_Connector(no load resitor) (J10.39)
TX_OUT54: 22_TMUX9832(0-64)_Pinout (U28.E10), 24_TX_Connector(no load resitor) (J9.82)
TX_OUT55: 22_TMUX9832(0-64)_Pinout (U28.F11), 24_TX_Connector(no load resitor) (J10.43)
TX_OUT56: 22_TMUX9832(0-64)_Pinout (U28.F10), 24_TX_Connector(no load resitor) (J9.78)
TX_OUT57: 22_TMUX9832(0-64)_Pinout (U28.G11), 24_TX_Connector(no load resitor) (J10.47)
TX_OUT58: 22_TMUX9832(0-64)_Pinout (U28.G10), 24_TX_Connector(no load resitor) (J9.74)
TX_OUT59: 22_TMUX9832(0-64)_Pinout (U28.H11), 24_TX_Connector(no load resitor) (J10.51)
TX_OUT60: 22_TMUX9832(0-64)_Pinout (U28.H10), 24_TX_Connector(no load resitor) (J9.70)
TX_OUT61: 22_TMUX9832(0-64)_Pinout (U28.J11), 24_TX_Connector(no load resitor) (J10.55)
TX_OUT62: 22_TMUX9832(0-64)_Pinout (U28.J10), 24_TX_Connector(no load resitor) (J9.66)
TX_OUT63: 22_TMUX9832(0-64)_Pinout (U28.K11), 24_TX_Connector(no load resitor) (J10.59)
TX_OUT64: 22_TMUX9832(0-64)_Pinout (U28.L11), 24_TX_Connector(no load resitor) (J9.62)
TX_OUT65: 23_TMUX9832(65-128)_Pinout (U27.L1), 24_TX_Connector(no load resitor) (J10.62)
TX_OUT66: 23_TMUX9832(65-128)_Pinout (U27.K1), 24_TX_Connector(no load resitor) (J9.59)
TX_OUT67: 23_TMUX9832(65-128)_Pinout (U27.J2), 24_TX_Connector(no load resitor) (J10.66)
TX_OUT68: 23_TMUX9832(65-128)_Pinout (U27.J1), 24_TX_Connector(no load resitor) (J9.55)
TX_OUT69: 23_TMUX9832(65-128)_Pinout (U27.H2), 24_TX_Connector(no load resitor) (J10.70)
TX_OUT70: 23_TMUX9832(65-128)_Pinout (U27.H1), 24_TX_Connector(no load resitor) (J9.51)
TX_OUT71: 23_TMUX9832(65-128)_Pinout (U27.G2), 24_TX_Connector(no load resitor) (J10.74)
TX_OUT72: 23_TMUX9832(65-128)_Pinout (U27.G1), 24_TX_Connector(no load resitor) (J9.47)
TX_OUT73: 23_TMUX9832(65-128)_Pinout (U27.F2), 24_TX_Connector(no load resitor) (J10.78)
TX_OUT74: 23_TMUX9832(65-128)_Pinout (U27.F1), 24_TX_Connector(no load resitor) (J9.43)
TX_OUT75: 23_TMUX9832(65-128)_Pinout (U27.E2), 24_TX_Connector(no load resitor) (J10.82)
TX_OUT76: 23_TMUX9832(65-128)_Pinout (U27.E1), 24_TX_Connector(no load resitor) (J9.39)
TX_OUT77: 23_TMUX9832(65-128)_Pinout (U27.D2), 24_TX_Connector(no load resitor) (J10.86)
TX_OUT78: 23_TMUX9832(65-128)_Pinout (U27.D1), 24_TX_Connector(no load resitor) (J9.35)
TX_OUT79: 23_TMUX9832(65-128)_Pinout (U27.C2), 24_TX_Connector(no load resitor) (J10.90)
TX_OUT80: 23_TMUX9832(65-128)_Pinout (U27.C1), 24_TX_Connector(no load resitor) (J9.31)
TX_OUT81: 23_TMUX9832(65-128)_Pinout (U27.C11), 24_TX_Connector(no load resitor) (J10.94)
TX_OUT82: 23_TMUX9832(65-128)_Pinout (U27.C10), 24_TX_Connector(no load resitor) (J9.27)
TX_OUT83: 23_TMUX9832(65-128)_Pinout (U27.D11), 24_TX_Connector(no load resitor) (J10.98)
TX_OUT84: 23_TMUX9832(65-128)_Pinout (U27.D10), 24_TX_Connector(no load resitor) (J9.23)
TX_OUT85: 23_TMUX9832(65-128)_Pinout (U27.E11), 24_TX_Connector(no load resitor) (J10.102)
TX_OUT86: 23_TMUX9832(65-128)_Pinout (U27.E10), 24_TX_Connector(no load resitor) (J9.19)
TX_OUT87: 23_TMUX9832(65-128)_Pinout (U27.F11), 24_TX_Connector(no load resitor) (J10.106)
TX_OUT88: 23_TMUX9832(65-128)_Pinout (U27.F10), 24_TX_Connector(no load resitor) (J9.15)
TX_OUT89: 23_TMUX9832(65-128)_Pinout (U27.G11), 24_TX_Connector(no load resitor) (J10.110)
TX_OUT90: 23_TMUX9832(65-128)_Pinout (U27.G10), 24_TX_Connector(no load resitor) (J9.11)
TX_OUT91: 23_TMUX9832(65-128)_Pinout (U27.H11), 24_TX_Connector(no load resitor) (J10.114)
TX_OUT92: 23_TMUX9832(65-128)_Pinout (U27.H10), 24_TX_Connector(no load resitor) (J9.7)
TX_OUT93: 23_TMUX9832(65-128)_Pinout (U27.J11), 24_TX_Connector(no load resitor) (J10.118)
TX_OUT94: 23_TMUX9832(65-128)_Pinout (U27.J10), 24_TX_Connector(no load resitor) (J9.3)
TX_OUT95: 23_TMUX9832(65-128)_Pinout (U27.K11), 24_TX_Connector(no load resitor) (J10.120)
TX_OUT96: 23_TMUX9832(65-128)_Pinout (U27.L11), 24_TX_Connector(no load resitor) (J9.1)
TX_OUT97: 23_TMUX9832(65-128)_Pinout (J15.1 U30.L1), 24_TX_Connector(no load resitor) (J10.61)
TX_OUT98: 23_TMUX9832(65-128)_Pinout (U30.K1), 24_TX_Connector(no load resitor) (J9.60)
TX_OUT99: 23_TMUX9832(65-128)_Pinout (U30.J2), 24_TX_Connector(no load resitor) (J10.65)
TX_OUT100: 23_TMUX9832(65-128)_Pinout (U30.J1), 24_TX_Connector(no load resitor) (J9.56)
TX_OUT101: 23_TMUX9832(65-128)_Pinout (U30.H2), 24_TX_Connector(no load resitor) (J10.69)
TX_OUT102: 23_TMUX9832(65-128)_Pinout (U30.H1), 24_TX_Connector(no load resitor) (J9.52)
TX_OUT103: 23_TMUX9832(65-128)_Pinout (U30.G2), 24_TX_Connector(no load resitor) (J10.73)
TX_OUT104: 23_TMUX9832(65-128)_Pinout (U30.G1), 24_TX_Connector(no load resitor) (J9.48)
TX_OUT105: 23_TMUX9832(65-128)_Pinout (U30.F2), 24_TX_Connector(no load resitor) (J10.77)
TX_OUT106: 23_TMUX9832(65-128)_Pinout (U30.F1), 24_TX_Connector(no load resitor) (J9.44)
TX_OUT107: 23_TMUX9832(65-128)_Pinout (U30.E2), 24_TX_Connector(no load resitor) (J10.81)
TX_OUT108: 23_TMUX9832(65-128)_Pinout (U30.E1), 24_TX_Connector(no load resitor) (J9.40)
TX_OUT109: 23_TMUX9832(65-128)_Pinout (U30.D2), 24_TX_Connector(no load resitor) (J10.85)
TX_OUT110: 23_TMUX9832(65-128)_Pinout (U30.D1), 24_TX_Connector(no load resitor) (J9.36)
TX_OUT111: 23_TMUX9832(65-128)_Pinout (U30.C2), 24_TX_Connector(no load resitor) (J10.89)
TX_OUT112: 23_TMUX9832(65-128)_Pinout (U30.C1), 24_TX_Connector(no load resitor) (J9.32)
TX_OUT113: 23_TMUX9832(65-128)_Pinout (U30.C11), 24_TX_Connector(no load resitor) (J10.93)
TX_OUT114: 23_TMUX9832(65-128)_Pinout (U30.C10), 24_TX_Connector(no load resitor) (J9.28)
TX_OUT115: 23_TMUX9832(65-128)_Pinout (U30.D11), 24_TX_Connector(no load resitor) (J10.97)
TX_OUT116: 23_TMUX9832(65-128)_Pinout (U30.D10), 24_TX_Connector(no load resitor) (J9.24)
TX_OUT117: 23_TMUX9832(65-128)_Pinout (U30.E11), 24_TX_Connector(no load resitor) (J10.101)
TX_OUT118: 23_TMUX9832(65-128)_Pinout (U30.E10), 24_TX_Connector(no load resitor) (J9.20)
TX_OUT119: 23_TMUX9832(65-128)_Pinout (U30.F11), 24_TX_Connector(no load resitor) (J10.105)
TX_OUT120: 23_TMUX9832(65-128)_Pinout (U30.F10), 24_TX_Connector(no load resitor) (J9.16)
TX_OUT121: 23_TMUX9832(65-128)_Pinout (U30.G11), 24_TX_Connector(no load resitor) (J10.109)
TX_OUT122: 23_TMUX9832(65-128)_Pinout (U30.G10), 24_TX_Connector(no load resitor) (J9.12)
TX_OUT123: 23_TMUX9832(65-128)_Pinout (U30.H11), 24_TX_Connector(no load resitor) (J10.113)
TX_OUT124: 23_TMUX9832(65-128)_Pinout (U30.H10), 24_TX_Connector(no load resitor) (J9.8)
TX_OUT125: 23_TMUX9832(65-128)_Pinout (U30.J11), 24_TX_Connector(no load resitor) (J10.117)
TX_OUT126: 23_TMUX9832(65-128)_Pinout (U30.J10), 24_TX_Connector(no load resitor) (J9.4)
TX_OUT127: 23_TMUX9832(65-128)_Pinout (U30.K11), 24_TX_Connector(no load resitor) (J10.119)
TX_OUT128: 23_TMUX9832(65-128)_Pinout (J17.1 R166.2 U30.L11), 24_TX_Connector(no load resitor) (J9.2)
V_-5V: 12_LowVoltage_PowerSupplies01 (7 pins), 20_TX7516_PartAPinout (FB13.1), 21_TX7516_PartBPinout (FB16.1)
VCC3P3_XDS: 14_XDS110_Debugger (37 pins), 18_AM243x_Pinout (6 pins)
VCORE_0.85V: 12_LowVoltage_PowerSupplies01 (C78.1 C79.1 C80.1 R56.2), 16_AM243x_Reset (R128.2), 17_AM243x_SocPower (46 pins)
VSYS_1.8V: 13_LowVoltage_PowerSupplies02 (8 pins), 16_AM243x_Reset (7 pins), 17_AM243x_SocPower (8 pins), 18_AM243x_Pinout (5 pins), 20_TX7516_PartAPinout (FB14.1), 21_TX7516_PartBPinout (FB17.1)
VSYS_3.3V: 11_HighVoltage_PowerSupply (11 pins), 13_LowVoltage_PowerSupplies02 (19 pins), 14_XDS110_Debugger (C114.1 U15.1 U15.3), 15_AM243x_BootMode (25 pins), 16_AM243x_Reset (5 pins), 17_AM243x_SocPower (FB3.1 FB10.1 R144.1), 18_AM243x_Pinout (12 pins), 19_Clock_Gen (R152.1 R153.1), 20_TX7516_PartAPinout (C459.1 R438.1 R439.1 U31.16), 22_TMUX9832(0-64)_Pinout (R165.1 R296.1), 23_TMUX9832(65-128)_Pinout (R162.1 R299.1)
VSYS_5V: 12_LowVoltage_PowerSupplies01 (9 pins), 16_AM243x_Reset (C121.1 R125.1 R457.2 U18.14), 17_AM243x_SocPower (R141.2), 20_TX7516_PartAPinout (FB12.1), 21_TX7516_PartBPinout (FB15.1), 22_TMUX9832(0-64)_Pinout (R164.1 R295.1), 23_TMUX9832(65-128)_Pinout (R161.1 R298.1)

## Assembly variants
Alternate oscillator: not fitted C39 R428 R429 R431 R432 R435 R436 R515 R516; alternate parts Y2 -> CMP-0088518-1
DNP test headers: not fitted C39 J7 J8 J13 J14 J15 J16 J17 J18 R428 R429 R431 R432 R435 R436 R515 R516
DNP test headers and DNP muxes: not fitted C39 J7 J8 J13 J14 J15 J16 J17 J18 R428 R429 R431 R432 R435 R436 R515 R516 U27 U28 U29 U30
